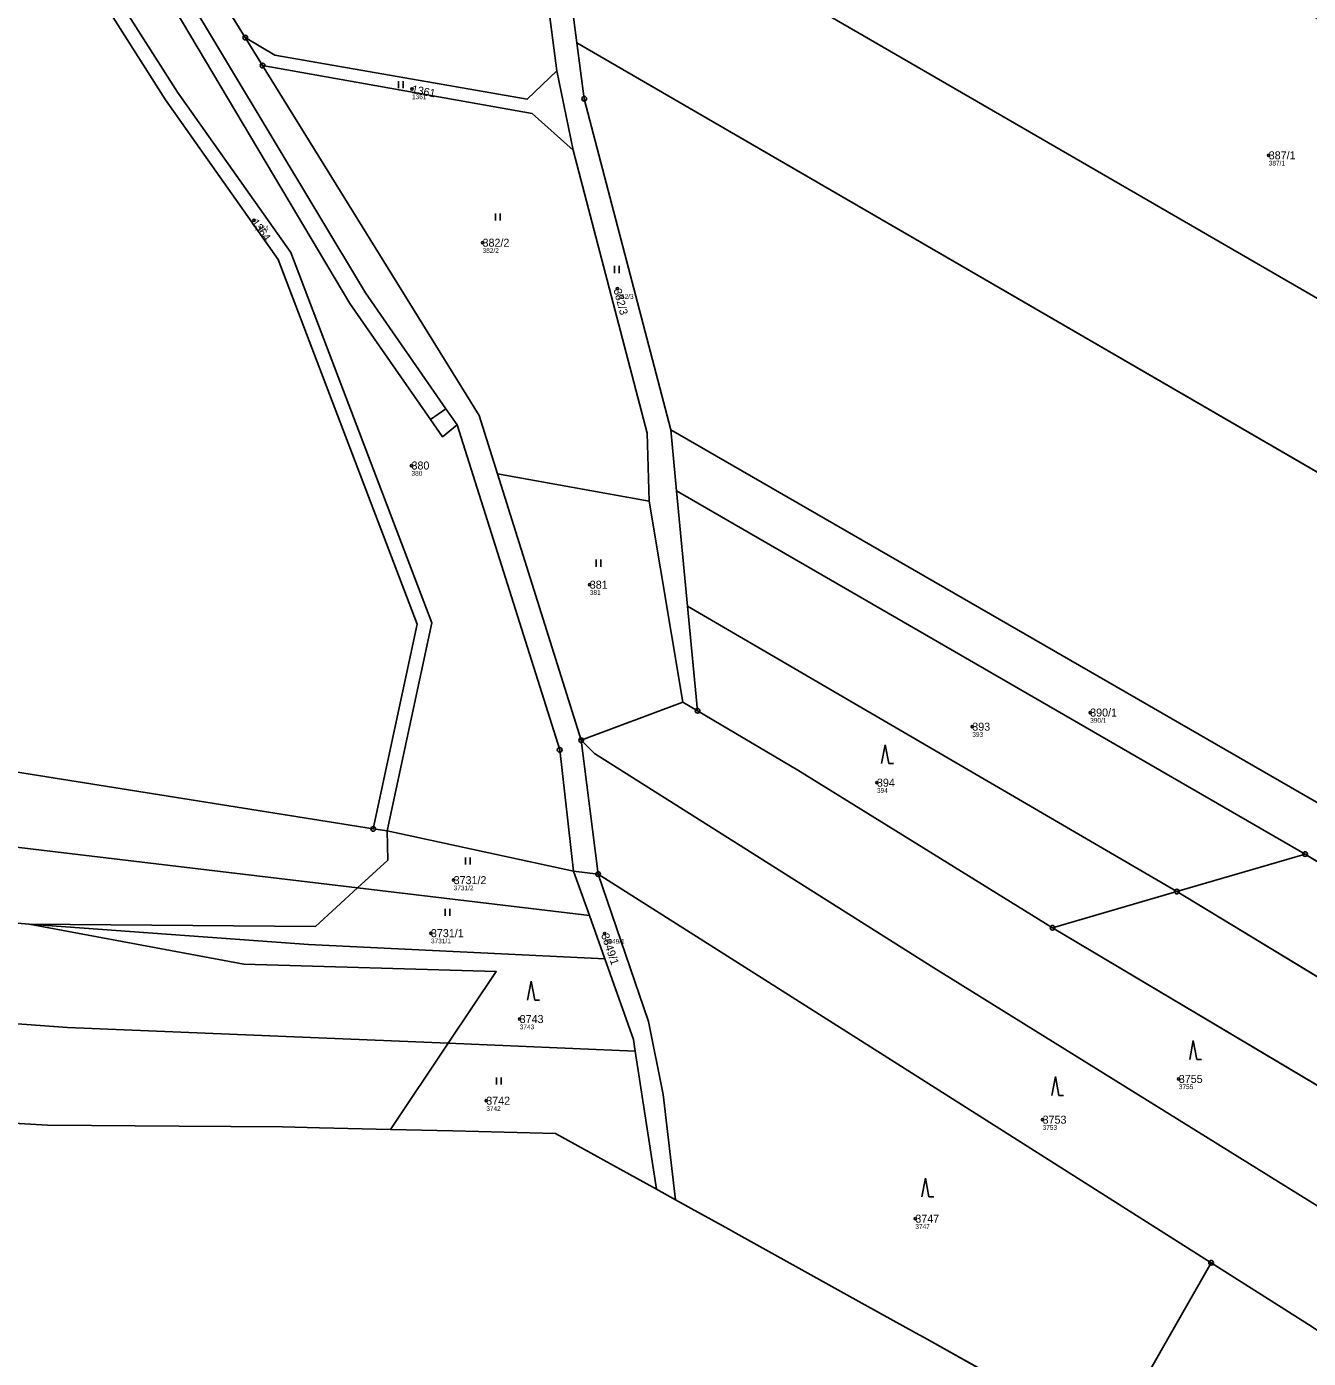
# Model space of a CAD drawing. Extents: x -658203 to -653176, y -1156738 to -1151709.
# Drawn here: x -653692.3 to -653420.1, y -1155498 to -1155215.2 of the extents above; entities that cross this region are included whole.
import ezdxf

# ---------------------------------------------------------------- set-up
doc = ezdxf.new("R2010")
doc.units = 0
for name, color, linetype in [('Vrstva 1', 7, 'Continuous'), ('Vrstva 2', 7, 'Continuous'), ('Vrstva 3', 7, 'Continuous'), ('Vrstva 4', 7, 'Continuous'), ('Vrstva 50', 7, 'Continuous'), ('Vrstva 51', 7, 'Continuous'), ('Vrstva 53', 7, 'Continuous'), ('Vrstva 8', 7, 'Continuous')]:
    doc.layers.add(name, color=color, linetype=linetype)

msp = doc.modelspace()

# ---------------------------------------------------------------- linework, layer by layer
at = {"layer": 'Vrstva 1'}
for p, q in [((-653645.85, -1155217.54), (-653673.29, -1155173.19)), ((-653585.63, -1155178.87), (-653579.71, -1155224.59)), ((-653575.44, -1155218.66), (-653580.63, -1155178.87)), ((-653642.18, -1155223.47), (-653645.85, -1155217.54)), ((-653575.44, -1155218.66), (-653285.64, -1155386.73)), ((-653596.22, -1155297.76), (-653642.18, -1155223.47)), ((-653642.18, -1155223.47), (-653584.97, -1155233.63)), ((-653579.71, -1155224.59), (-653576.24, -1155241.41)), ((-653584.97, -1155233.63), (-653576.24, -1155241.41)), ((-653592.31, -1155310.2), (-653596.22, -1155297.76)), ((-653554.27, -1155313.81), (-653555.51, -1155300.8)), ((-653574.51, -1155366.76), (-653592.31, -1155310.2)), ((-653560.1, -1155315.95), (-653592.31, -1155310.2)), ((-653551.93, -1155338.26), (-653554.27, -1155313.81)), ((-653554.27, -1155313.81), (-653420.83, -1155390.93)), ((-653560.1, -1155315.95), (-653552.95, -1155358.63)), ((-653448.08, -1155398.88), (-653551.93, -1155338.26)), ((-653549.81, -1155360.49), (-653551.93, -1155338.26)), ((-653552.95, -1155358.63), (-653574.51, -1155366.76)), ((-653549.81, -1155360.49), (-653552.95, -1155358.63)), ((-653570.95, -1155395.18), (-653574.51, -1155366.76)), ((-653615.76, -1155386.01), (-653618.68, -1155385.57)), ((-653576.16, -1155394.52), (-653615.76, -1155386.01)), ((-653420.83, -1155390.93), (-653448.08, -1155398.88)), ((-653362.28, -1155427.19), (-653420.83, -1155390.93)), ((-653576.16, -1155394.52), (-653570.95, -1155395.18)), ((-653572.8, -1155404), (-653576.16, -1155394.52)), ((-653440.8, -1155477.72), (-653570.95, -1155395.18)), ((-653572.8, -1155404), (-653622.01, -1155398.07)), ((-653448.08, -1155398.88), (-653474.46, -1155406.57)), ((-653310.81, -1155482.23), (-653448.08, -1155398.88)), ((-653569.54, -1155413.18), (-653572.8, -1155404)), ((-653323.55, -1155496.42), (-653474.46, -1155406.57)), ((-653615.03, -1155449.39), (-653602.75, -1155431.07)), ((-653563.07, -1155432.81), (-653602.75, -1155431.07)), ((-653558.56, -1155462.1), (-653563.07, -1155432.81)), ((-653687.81, -1155448.47), (-653740.77, -1155445.38)), ((-653659.86, -1155448.68), (-653687.81, -1155448.47)), ((-653615.03, -1155449.39), (-653630.08, -1155449.03)), ((-653601.76, -1155449.71), (-653615.03, -1155449.39)), ((-653579.97, -1155450.24), (-653601.76, -1155449.71)), ((-653565.59, -1155458.2), (-653579.97, -1155450.24)), ((-653558.56, -1155462.1), (-653565.59, -1155458.2)), ((-653554.48, -1155464.36), (-653558.56, -1155462.1)), ((-653514.32, -1155486.62), (-653541.72, -1155471.43)), ((-653440.8, -1155477.72), (-653462.39, -1155515.62)), ((-653462.39, -1155515.62), (-653501.74, -1155493.61))]:
    msp.add_line(p, q, dxfattribs=at)
for points in [[(-653783.57, -1155112.28), (-653754.65, -1155121.98), (-653682.01, -1155169.28), (-653679.57, -1155173.07), (-653620.34, -1155271.71), (-653603.24, -1155296.36), (-653600.85, -1155299.8)], [(-653580.63, -1155178.87), (-653417.73, -1155273.23), (-653345.85, -1155313.63), (-653281.19, -1155352.07)], [(-653675.36, -1155186.93), (-653623.63, -1155273.99), (-653606.53, -1155298.64), (-653603.98, -1155302.31), (-653600.85, -1155299.8)], [(-653675.36, -1155186.93), (-653674.8, -1155206.17), (-653660.26, -1155229.1), (-653636.19, -1155263.19), (-653606.23, -1155341.79), (-653615.76, -1155386.01)], [(-653618.68, -1155385.57), (-653609.35, -1155342.13), (-653638.9, -1155264.67), (-653662.81, -1155230.74), (-653677.73, -1155207.19)], [(-653645.85, -1155217.54), (-653639.58, -1155221.28), (-653585.99, -1155230.62), (-653579.71, -1155224.59)], [(-653555.51, -1155300.8), (-653573.89, -1155230.52), (-653575.44, -1155218.66)], [(-653576.24, -1155241.41), (-653560.52, -1155301.52), (-653560.1, -1155315.95)], [(-653600.85, -1155299.8), (-653579.1, -1155368.79), (-653576.16, -1155394.52)], [(-653555.51, -1155300.8), (-653410.6, -1155384.41), (-653353.51, -1155411.52)], [(-653618.68, -1155385.57), (-653730.25, -1155367.83), (-653828.77, -1155354.8), (-653848.31, -1155352.36)], [(-653474.46, -1155406.57), (-653528.55, -1155373.14), (-653549.81, -1155360.49)], [(-653337.28, -1155515.94), (-653500.2, -1155414.73), (-653571.68, -1155369.56), (-653574.51, -1155366.76)], [(-653837.75, -1155369.31), (-653763.99, -1155381.2), (-653622.01, -1155398.07)], [(-653843.39, -1155387.19), (-653779.58, -1155396.41), (-653732.45, -1155402.41), (-653691.76, -1155405.84)], [(-653622.01, -1155398.07), (-653615.6, -1155392.19), (-653615.76, -1155386.01)], [(-653570.95, -1155395.18), (-653560.26, -1155426.46), (-653557.11, -1155441.97), (-653554.48, -1155464.36)], [(-653691.76, -1155405.84), (-653630.97, -1155406.29), (-653622.01, -1155398.07)], [(-653691.76, -1155405.84), (-653632.42, -1155410.1), (-653569.54, -1155413.18)], [(-653602.75, -1155431.07), (-653592.57, -1155415.88), (-653646.16, -1155414.28), (-653691.76, -1155405.84)], [(-653563.07, -1155432.81), (-653563.46, -1155430.31), (-653569.54, -1155413.18)], [(-653808.51, -1155418.6), (-653683.6, -1155427.72), (-653602.75, -1155431.07)], [(-653630.08, -1155449.03), (-653637.95, -1155448.84), (-653659.86, -1155448.68)], [(-653541.72, -1155471.43), (-653543.2, -1155470.61), (-653551.18, -1155466.19), (-653554.48, -1155464.36)], [(-653390.75, -1155510.07), (-653420.12, -1155490.83), (-653440.8, -1155477.72)], [(-653501.74, -1155493.61), (-653503.54, -1155492.6), (-653514.32, -1155486.62)]]:
    msp.add_lwpolyline(points, dxfattribs=at)
at = {"layer": 'Vrstva 3'}
for p, q in [((-653613.32, -1155228.31), (-653613.32, -1155226.81)), ((-653612.32, -1155228.31), (-653612.32, -1155226.81)), ((-653592.73, -1155256.37), (-653592.73, -1155254.87)), ((-653591.73, -1155256.37), (-653591.73, -1155254.87)), ((-653567.46, -1155267.53), (-653567.46, -1155266.03)), ((-653566.46, -1155267.53), (-653566.46, -1155266.03)), ((-653571.35, -1155329.89), (-653571.35, -1155328.39)), ((-653570.35, -1155329.89), (-653570.35, -1155328.39)), ((-653510, -1155367.71), (-653510.75, -1155371.71)), ((-653509.25, -1155371.71), (-653510, -1155367.71)), ((-653509.25, -1155371.71), (-653508.25, -1155371.71)), ((-653599.11, -1155393.13), (-653599.11, -1155391.63)), ((-653598.11, -1155393.13), (-653598.11, -1155391.63)), ((-653603.4, -1155404.07), (-653603.4, -1155402.57)), ((-653602.4, -1155404.07), (-653602.4, -1155402.57)), ((-653585.15, -1155417.93), (-653585.9, -1155421.93)), ((-653584.4, -1155421.93), (-653585.15, -1155417.93)), ((-653584.4, -1155421.93), (-653583.4, -1155421.93)), ((-653444.59, -1155430.53), (-653445.34, -1155434.53)), ((-653443.84, -1155434.53), (-653444.59, -1155430.53)), ((-653443.84, -1155434.53), (-653442.84, -1155434.53)), ((-653592.5, -1155439.88), (-653592.5, -1155438.38)), ((-653591.5, -1155439.88), (-653591.5, -1155438.38)), ((-653473.86, -1155438.17), (-653474.61, -1155442.17)), ((-653473.11, -1155442.17), (-653473.86, -1155438.17)), ((-653473.11, -1155442.17), (-653472.11, -1155442.17)), ((-653501.45, -1155459.72), (-653502.2, -1155463.72)), ((-653500.7, -1155463.72), (-653501.45, -1155459.72)), ((-653500.7, -1155463.72), (-653499.7, -1155463.72))]:
    msp.add_line(p, q, dxfattribs=at)
at = {"layer": 'Vrstva 4'}
msp.add_line((-653606.53, -1155298.64), (-653603.24, -1155296.36), dxfattribs=at)
at = {"layer": 'Vrstva 50'}
for centre in [(-653610.46, -1155228.46), (-653428.56, -1155242.54), (-653643.97, -1155256.33), (-653595.47, -1155261.1), (-653566.86, -1155270.87), (-653610.56, -1155308.41), (-653572.71, -1155333.72), (-653466.47, -1155360.87), (-653491.5, -1155363.87), (-653511.74, -1155375.76), (-653601.61, -1155396.46), (-653606.43, -1155407.72), (-653569.53, -1155407.81), (-653587.59, -1155425.96), (-653447.65, -1155438.68), (-653594.68, -1155443.3), (-653476.57, -1155447.33), (-653503.59, -1155468.35)]:
    msp.add_circle(centre, 0.25, dxfattribs=at)
at = {"layer": 'Vrstva 51'}
msp.add_lwpolyline([(-654033.15, -1155070.56), (-653787.42, -1155115.69), (-653780.87, -1155118.05), (-653757.27, -1155125.53), (-653682.44, -1155175.51), (-653678.48, -1155181.89), (-653675.36, -1155186.93), (-653623.63, -1155273.99), (-653606.53, -1155298.64), (-653603.98, -1155302.31), (-653600.85, -1155299.8), (-653603.24, -1155296.36), (-653620.34, -1155271.71), (-653679.57, -1155173.07), (-653682.01, -1155169.28), (-653754.65, -1155121.98), (-653783.57, -1155112.28), (-653829.98, -1155103.75), (-653849.16, -1155100.23), (-653863.81, -1155097.54), (-653945.81, -1155082.48)], dxfattribs=at)
for points in [[(-653630.16, -1155090.31), (-653633.58, -1155094.62), (-653631.28, -1155099.66), (-653571.65, -1155138.74), (-653580.97, -1155176.3), (-653580.63, -1155178.87), (-653417.73, -1155273.23), (-653345.85, -1155313.63), (-653281.19, -1155352.07), (-653279.11, -1155318.71), (-653278.39, -1155294.76)], [(-653645.85, -1155217.54), (-653673.29, -1155173.19), (-653675.86, -1155169.03), (-653730.63, -1155132.02), (-653737.17, -1155127.6), (-653752.77, -1155117.07), (-653783.57, -1155112.28), (-653754.65, -1155121.98), (-653682.01, -1155169.28), (-653679.57, -1155173.07), (-653620.34, -1155271.71), (-653603.24, -1155296.36), (-653600.85, -1155299.8), (-653579.1, -1155368.79), (-653576.16, -1155394.52), (-653570.95, -1155395.18), (-653574.51, -1155366.76), (-653592.31, -1155310.2), (-653596.22, -1155297.76), (-653642.18, -1155223.47)], [(-653609.35, -1155342.13), (-653638.9, -1155264.67), (-653662.81, -1155230.74), (-653677.73, -1155207.19), (-653692.31, -1155203.5), (-653719.58, -1155176.69), (-653762.74, -1155148.69), (-653791.92, -1155141.4), (-653891.15, -1155221.05), (-653890.58, -1155223.46), (-653811.62, -1155233.12), (-653814.02, -1155263.41), (-653819, -1155293.62), (-653835.81, -1155291.69), (-653838.72, -1155305.82), (-653848.31, -1155352.36), (-653828.77, -1155354.8), (-653730.25, -1155367.83), (-653618.68, -1155385.57)], [(-653580.63, -1155178.87), (-653580.97, -1155176.3), (-653584.62, -1155170.25), (-653586.02, -1155175.89), (-653585.63, -1155178.87), (-653579.71, -1155224.59), (-653576.24, -1155241.41), (-653560.52, -1155301.52), (-653560.1, -1155315.95), (-653552.95, -1155358.63), (-653549.81, -1155360.49), (-653551.93, -1155338.26), (-653554.27, -1155313.81), (-653555.51, -1155300.8), (-653573.89, -1155230.52), (-653575.44, -1155218.66)], [(-653579.71, -1155224.59), (-653585.63, -1155178.87), (-653673.29, -1155173.19), (-653645.85, -1155217.54), (-653639.58, -1155221.28), (-653585.99, -1155230.62)], [(-653285.64, -1155386.73), (-653281.19, -1155352.07), (-653345.85, -1155313.63), (-653417.73, -1155273.23), (-653580.63, -1155178.87), (-653575.44, -1155218.66)], [(-653675.36, -1155186.93), (-653678.48, -1155181.89), (-653677.73, -1155207.19), (-653662.81, -1155230.74), (-653638.9, -1155264.67), (-653609.35, -1155342.13), (-653618.68, -1155385.57), (-653615.76, -1155386.01), (-653606.23, -1155341.79), (-653636.19, -1155263.19), (-653660.26, -1155229.1), (-653674.8, -1155206.17)], [(-653606.23, -1155341.79), (-653615.76, -1155386.01), (-653576.16, -1155394.52), (-653579.1, -1155368.79), (-653600.85, -1155299.8), (-653603.98, -1155302.31), (-653606.53, -1155298.64), (-653623.63, -1155273.99), (-653675.36, -1155186.93), (-653674.8, -1155206.17), (-653660.26, -1155229.1), (-653636.19, -1155263.19)], [(-653584.97, -1155233.63), (-653576.24, -1155241.41), (-653579.71, -1155224.59), (-653585.99, -1155230.62), (-653639.58, -1155221.28), (-653645.85, -1155217.54), (-653642.18, -1155223.47)], [(-653353.51, -1155411.52), (-653347.9, -1155414.18), (-653320.84, -1155428.37), (-653293.13, -1155445.09), (-653285.64, -1155386.73), (-653575.44, -1155218.66), (-653573.89, -1155230.52), (-653555.51, -1155300.8), (-653410.6, -1155384.41)], [(-653596.22, -1155297.76), (-653592.31, -1155310.2), (-653560.1, -1155315.95), (-653560.52, -1155301.52), (-653576.24, -1155241.41), (-653584.97, -1155233.63), (-653642.18, -1155223.47)], [(-653554.27, -1155313.81), (-653420.83, -1155390.93), (-653362.28, -1155427.19), (-653353.51, -1155411.52), (-653410.6, -1155384.41), (-653555.51, -1155300.8)], [(-653560.1, -1155315.95), (-653592.31, -1155310.2), (-653574.51, -1155366.76), (-653552.95, -1155358.63)], [(-653448.08, -1155398.88), (-653420.83, -1155390.93), (-653554.27, -1155313.81), (-653551.93, -1155338.26)], [(-653448.08, -1155398.88), (-653551.93, -1155338.26), (-653549.81, -1155360.49), (-653528.55, -1155373.14), (-653474.46, -1155406.57)], [(-653763.99, -1155381.2), (-653622.01, -1155398.07), (-653615.6, -1155392.19), (-653615.76, -1155386.01), (-653618.68, -1155385.57), (-653730.25, -1155367.83), (-653828.77, -1155354.8), (-653848.31, -1155352.36), (-653851.42, -1155367.49), (-653837.75, -1155369.31)], [(-653323.55, -1155496.42), (-653474.46, -1155406.57), (-653528.55, -1155373.14), (-653549.81, -1155360.49), (-653552.95, -1155358.63), (-653574.51, -1155366.76), (-653571.68, -1155369.56), (-653500.2, -1155414.73), (-653337.28, -1155515.94)], [(-653732.45, -1155402.41), (-653691.76, -1155405.84), (-653630.97, -1155406.29), (-653622.01, -1155398.07), (-653763.99, -1155381.2), (-653837.75, -1155369.31), (-653851.42, -1155367.49), (-653855.21, -1155385.9), (-653843.39, -1155387.19), (-653779.58, -1155396.41)], [(-653571.68, -1155369.56), (-653574.51, -1155366.76), (-653570.95, -1155395.18), (-653440.8, -1155477.72), (-653420.12, -1155490.83), (-653390.75, -1155510.07), (-653351.23, -1155535.97), (-653337.28, -1155515.94), (-653500.2, -1155414.73)], [(-653824.86, -1155403.31), (-653806.04, -1155410.01), (-653808.51, -1155418.6), (-653683.6, -1155427.72), (-653602.75, -1155431.07), (-653592.57, -1155415.88), (-653646.16, -1155414.28), (-653691.76, -1155405.84), (-653732.45, -1155402.41), (-653779.58, -1155396.41), (-653843.39, -1155387.19), (-653847.33, -1155397.98)], [(-653615.76, -1155386.01), (-653615.6, -1155392.19), (-653622.01, -1155398.07), (-653572.8, -1155404), (-653576.16, -1155394.52)], [(-653420.83, -1155390.93), (-653448.08, -1155398.88), (-653310.81, -1155482.23), (-653297.92, -1155467.88), (-653356.01, -1155431.07), (-653362.28, -1155427.19)], [(-653569.54, -1155413.18), (-653563.46, -1155430.31), (-653563.07, -1155432.81), (-653558.56, -1155462.1), (-653554.48, -1155464.36), (-653557.11, -1155441.97), (-653560.26, -1155426.46), (-653570.95, -1155395.18), (-653576.16, -1155394.52), (-653572.8, -1155404)], [(-653570.95, -1155395.18), (-653560.26, -1155426.46), (-653557.11, -1155441.97), (-653554.48, -1155464.36), (-653551.18, -1155466.19), (-653543.2, -1155470.61), (-653541.72, -1155471.43), (-653514.32, -1155486.62), (-653503.54, -1155492.6), (-653501.74, -1155493.61), (-653462.39, -1155515.62), (-653440.8, -1155477.72)], [(-653569.54, -1155413.18), (-653572.8, -1155404), (-653622.01, -1155398.07), (-653630.97, -1155406.29), (-653691.76, -1155405.84), (-653632.42, -1155410.1)], [(-653310.81, -1155482.23), (-653448.08, -1155398.88), (-653474.46, -1155406.57), (-653323.55, -1155496.42)], [(-653563.46, -1155430.31), (-653569.54, -1155413.18), (-653632.42, -1155410.1), (-653691.76, -1155405.84), (-653646.16, -1155414.28), (-653592.57, -1155415.88), (-653602.75, -1155431.07), (-653563.07, -1155432.81)], [(-653740.77, -1155445.38), (-653687.81, -1155448.47), (-653659.86, -1155448.68), (-653637.95, -1155448.84), (-653630.08, -1155449.03), (-653615.03, -1155449.39), (-653602.75, -1155431.07), (-653683.6, -1155427.72), (-653808.51, -1155418.6), (-653811.96, -1155430.6), (-653818.33, -1155440.6), (-653815.97, -1155440.75), (-653796.77, -1155441.93), (-653772.56, -1155443.42), (-653748.76, -1155444.89)], [(-653558.56, -1155462.1), (-653563.07, -1155432.81), (-653602.75, -1155431.07), (-653615.03, -1155449.39), (-653601.76, -1155449.71), (-653579.97, -1155450.24), (-653565.59, -1155458.2)], [(-653390.75, -1155510.07), (-653420.12, -1155490.83), (-653440.8, -1155477.72), (-653462.39, -1155515.62), (-653455.79, -1155519.32), (-653439.5, -1155528.43), (-653417.61, -1155540.67), (-653430.32, -1155568.94), (-653417.88, -1155573.53)]]:
    msp.add_lwpolyline(points, close=True, dxfattribs=at)
at = {"layer": 'Vrstva 53'}
msp.add_lwpolyline([(-653740.77, -1155445.38), (-653687.81, -1155448.47), (-653659.86, -1155448.68), (-653637.95, -1155448.84), (-653630.08, -1155449.03), (-653615.03, -1155449.39), (-653601.76, -1155449.71), (-653579.97, -1155450.24), (-653565.59, -1155458.2), (-653558.56, -1155462.1), (-653554.48, -1155464.36), (-653551.18, -1155466.19), (-653543.2, -1155470.61), (-653541.72, -1155471.43), (-653514.32, -1155486.62), (-653503.54, -1155492.6), (-653501.74, -1155493.61), (-653462.39, -1155515.62)], dxfattribs=at)
at = {"layer": 'Vrstva 8'}
for centre, radius in [((-653645.85, -1155217.54), 0.5), ((-653645.85, -1155217.54), 0.0303), ((-653642.18, -1155223.47), 0.5), ((-653642.18, -1155223.47), 0.0303), ((-653573.89, -1155230.52), 0.5), ((-653573.89, -1155230.52), 0.0303), ((-653549.81, -1155360.49), 0.5), ((-653549.81, -1155360.49), 0.0303), ((-653579.1, -1155368.79), 0.5), ((-653574.51, -1155366.76), 0.5), ((-653574.51, -1155366.76), 0.0303), ((-653579.1, -1155368.79), 0.0303), ((-653618.68, -1155385.57), 0.5), ((-653618.68, -1155385.57), 0.0303), ((-653420.83, -1155390.93), 0.5), ((-653420.83, -1155390.93), 0.0303), ((-653570.95, -1155395.18), 0.5), ((-653570.95, -1155395.18), 0.0303), ((-653448.08, -1155398.88), 0.5), ((-653448.08, -1155398.88), 0.0303), ((-653474.46, -1155406.57), 0.5), ((-653474.46, -1155406.57), 0.0303), ((-653440.8, -1155477.72), 0.5), ((-653440.8, -1155477.72), 0.0303)]:
    msp.add_circle(centre, radius, dxfattribs=at)

# ---------------------------------------------------------------- texts
at = {"layer": 'Vrstva 2'}
for s, rotation, p in [('1361', 349, (-653610.62, -1155229.29)), ('1364', 306, (-653644.66, -1155256.83)), ('382/3', 285, (-653567.68, -1155271.09)), ('3849/1', 289, (-653570.33, -1155408.09))]:
    msp.add_text(s, height=1.7, rotation=rotation, dxfattribs=at).set_placement(p)
for s, p in [('387/1', (-653428.56, -1155243.39)), ('382/2', (-653595.47, -1155261.95)), ('380', (-653610.56, -1155309.26)), ('381', (-653572.71, -1155334.57)), ('390/1', (-653466.47, -1155361.72)), ('393', (-653491.5, -1155364.72)), ('394', (-653511.74, -1155376.61)), ('3731/2', (-653601.61, -1155397.31)), ('3731/1', (-653606.43, -1155408.57)), ('3743', (-653587.59, -1155426.81)), ('3755', (-653447.65, -1155439.53)), ('3742', (-653594.68, -1155444.15)), ('3753', (-653476.57, -1155448.18)), ('3747', (-653503.59, -1155469.2))]:
    msp.add_text(s, height=1.7, dxfattribs=at).set_placement(p)
at = {"layer": 'Vrstva 50'}
for s, p in [('1361', (-653610.46, -1155230.62)), ('387/1', (-653428.56, -1155244.7)), ('1364', (-653643.97, -1155258.49)), ('382/2', (-653595.47, -1155263.26)), ('382/3', (-653566.86, -1155273.03)), ('380', (-653610.56, -1155310.57)), ('381', (-653572.71, -1155335.88)), ('390/1', (-653466.47, -1155363.03)), ('393', (-653491.5, -1155366.03)), ('394', (-653511.74, -1155377.92)), ('3731/2', (-653601.61, -1155398.62)), ('3731/1', (-653606.43, -1155409.88)), ('3849/1', (-653569.53, -1155409.97)), ('3743', (-653587.59, -1155428.12)), ('3755', (-653447.65, -1155440.84)), ('3742', (-653594.68, -1155445.46)), ('3753', (-653476.57, -1155449.49)), ('3747', (-653503.59, -1155470.51))]:
    msp.add_text(s, height=1, dxfattribs=at).set_placement(p)

doc.saveas('drawing.dxf')
